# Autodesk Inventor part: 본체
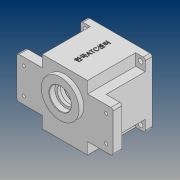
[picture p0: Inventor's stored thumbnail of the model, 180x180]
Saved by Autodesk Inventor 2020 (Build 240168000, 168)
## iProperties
Created: 2020-07
Part Number: 본체
Material: 일반
Document SubType Name: Modeling
Designer: PC312-
Density: 1 g/cm^3
Appearance: 기본값
Mass: 324.617 g
Surface Area: 793.597 cm^2
Volume: 324.617 cm^3
Author: PC312-
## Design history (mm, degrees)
sketch "스케치2"
  geometry: L1 (-47, 47)-(47, 47); L2 (47, 47)-(47, -47); L3 (47, -47)-(-47, -47); L4 (-47, -47)-(-47, 47); L5 (-47, 47)-(47, -47); L6 (47, 47)-(-47, -47); 1 further point
  constraints: 12 end point, 2 midpoint, 2 parallel, 1 horizontal, 1 perpendicular
  dimensions: "d0" = 94 distance of L2.end L3.end; "d1" = 94 distance of L1.end L2.end
extrude "돌출1" new body sketch "스케치2" stored distance "d2" = 80; taper "d3" = 0 deg
sketch "스케치3"
  geometry: L1 (-70, 30)-(70, 30); L2 (70, 30)-(70, -30); L3 (70, -30)-(-70, -30); L4 (-70, -30)-(-70, 30); L5 (-70, 30)-(70, -30); L6 (70, 30)-(-70, -30); 1 further point
  constraints: 12 end point, 2 midpoint, 2 parallel, 1 horizontal, 1 perpendicular
  dimensions: "d4" = 140 distance of L2.end L3.end; "d5" = 60 distance of L1.end L2.end
extrude "돌출2" join sketch "스케치3" distance "d6" = 13; taper "d7" = 0 deg
sketch "스케치4"
  geometry: L1 (47, 47)-(-47, 47) reference; L2 (33, 47)-(33, 30); L3 (33, 30)-(49.544, 30); L4 (70, 30)-(47, 30) reference; L5 (47, 30)-(47, 47) reference; L6 (-47, -47)-(-47, 47) reference; L7 (-47, 30)-(-33, 30); L8 (-33, 47)-(-33, 30); 2 further points
  constraints: 8 end point, 4 point on line, 2 vertical, 1 horizontal
  dimensions: "d8" = 33 distance from line of L2 point (0, 0); "d9" = 30 distance from line of point (0, 0) L3; "d12" = 33 distance from line of L8 point (0, 0); "d13" = 30 distance from line of point (0, 0) L7
extrude "돌출3" cut sketch "스케치4" distance "d10" = 70; taper "d11" = 0 deg
sketch "스케치5"
  geometry: C1 r 43 at (0, 0); C2 r 40 at (0, 0); 1 further point
  constraints: 2 centre point, 2 coincident
  dimensions: "d20" = 86 diameter of C1; "d21" = 80 diameter of C2
extrude "돌출4" cut sketch "스케치5" distance "d22" = 9; taper "d23" = 0 deg
extrude "돌출5" cut sketch "스케치5" distance "d24" = 71; taper "d25" = 0 deg
sketch "스케치6"
  geometry: A1 r 21 centre (0, 11) between (8.978, -7.984) and (-8.978, -7.984); A2 r 15 centre (0, -20) between (-8.978, -7.984) and (8.978, -7.984); 1 further point
  constraints: 4 point on circle, 2 centre point, 2 vertical alignment
  dimensions: "d26" = 42 diameter of A1; "d27" = 30 diameter of A2; "d28" = 11 distance of point (0, 0) A1.centre; "d29" = 20 distance of A2.centre point (0, 0)
extrude "돌출6" join sketch "스케치6" distance "d30" = 7; taper "d31" = 0 deg
sketch "스케치7"
  geometry: C1 r 17.5 at (0, 11); C2 r 11 at (0, -20); C3 r 12.5 at (0, 11); C4 r 9.5 at (0, -20); A1 r 21 centre (0, 11) between (8.978, -7.984) and (-8.978, -7.984) reference; A2 r 15 centre (0, -20) between (-8.978, -7.984) and (8.978, -7.984) reference; 1 further point
  constraints: 4 centre point, 4 coincident
  dimensions: "d32" = 35 diameter of C1; "d33" = 22 diameter of C2; "d34" = 25 diameter of C3; "d35" = 19 diameter of C4
extrude "돌출7" cut sketch "스케치7" distance "d36" = 10; taper "d37" = 0 deg
extrude "돌출8" cut sketch "스케치7" distance "d38" = 14.7; taper "d39" = 0 deg
extrude "돌출11" cut sketch "스케치7" distance "d44" = 7; taper "d45" = 0 deg
extrude "돌출12" cut sketch "스케치7" distance "d46" = 10; taper "d47" = 0 deg
sketch "스케치8"
  geometry: C1 r 27.5 at (0, 11); 1 further point
  constraints: 1 centre point, 1 vertical alignment
  dimensions: "d48" = 55 diameter of C1; "d49" = 11 distance of point (0, 0) C1.centre
extrude "돌출13" join sketch "스케치8" distance "d50" = 7; taper "d51" = 0 deg
sketch "스케치9"
  geometry: C1 r 27.5 at (0, 0) reference; C2 r 16 at (0, 0); 1 further point
  constraints: 1 centre point, 1 coincident
  dimensions: "d52" = 32 diameter of C2
extrude "돌출14" cut sketch "스케치9" distance "d53" = 8.3; taper "d54" = 0 deg
sketch "스케치10"
  geometry: A1 r 4 centre (-36, 0) between (-36.19, -3.995) and (-36.19, 3.995); A2 r 3 centre (-36.333, 6.992) between (-39.279, 7.559) and (-36.19, 3.995); A3 r 3 centre (-36.333, -6.992) between (-36.19, -3.995) and (-39.279, -7.559); A4 r 40 centre (0, 0) between (-39.279, 7.559) and (-39.279, -7.559) reference; 1 further point
  constraints: 8 point on circle, 4 tangent, 3 centre point, 1 horizontal alignment
  dimensions: "d55" = 8 diameter of A1; "d56" = 36 distance of point (0, 0) A1.centre; "d57" = 6 diameter of A2; "d58" = 6 diameter of A3
extrude "돌출15" join sketch "스케치10" distance "d59" = 62; taper "d60" = 0 deg
sketch "스케치11"
  geometry: C1 r 3.5 at (-40, 40); 1 further point
  constraints: 1 centre point
  dimensions: "d61" = 7 diameter of C1; "d62" = 40 horizontal distance of C1.centre point (0, 0); "d63" = 40 horizontal distance of C1.centre point (0, 0)
extrude "돌출16" cut sketch "스케치11" extent not by distance; stored distance "d64" = 0; taper "d65" = 0 deg
sketch "스케치12"
  geometry: 2 further points
  dimensions: "d72" = 60 horizontal distance of point (-60, 19) point (0, 0); "d73" = 19 vertical distance of point (-60, 19) point (0, 0)
hole "구멍1" sketch "스케치12" at (-60, 19) diameter "d74" = 4.5; stored, may be unused: countersink angle "d78" = 90 deg, drill point angle "d80" = 118 deg; dims "d75" = 7, "d76" = 10, "d77" = 5, "d79" = 9
sketch "스케치13"
  geometry: A1 r 4 centre (-36, 0) between (-36.19, -3.995) and (-36.19, 3.995) reference; 2 further points
  constraints: 1 coincident
hole "구멍2" sketch "스케치13" at (-36, 0) diameter "d87" = 3.242; stored, may be unused: countersink angle "d91" = 90 deg, drill point angle "d93" = 118 deg; dims "d88" = 7, "d89" = 10, "d90" = 5, "d92" = 9
node "작업 평면1"
sketch "스케치15"
  geometry: L1 (0, 0)-(94, 0) reference; 2 further points
  constraints: 1 coincident, 1 other
  dimensions: "d95" = 40 distance from line of L1 point (47, -40)
feature "엠보싱1" sketch "스케치15" dims "d8" = 33, "d9" = 30, "d96" = 0.5, "d97" = 0
chamfer "모따기2" distance "d101" = 1; stored, may be unused: second distance "d102" = 2, angle "d103" = 30 deg
chamfer "모따기3" distance "d104" = 1; stored, may be unused: second distance "d105" = 2, angle "d106" = 30 deg
fillet "모깎기1" dims "d107" = 3
fillet "모깎기2" dims "d108" = 3
fillet "모깎기3" dims "d109" = 3
chamfer "모따기4" distance "d110" = 0.8; stored, may be unused: second distance "d111" = 2, angle "d112" = 30 deg
node "솔리드1"
pattern_linear "직사각형 패턴1" dims "d16" = 80, "d19" = 77
mirror "미러1"
pattern_linear "직사각형 패턴2" dims "d68" = 80, "d71" = 80
pattern_linear "직사각형 패턴3" dims "d83" = 120, "d86" = 38
mirror "미러2"
feature "A9D066F2-1C7D-4E18-AEED-F7BC21143FA4" dims "d74" = 4.5, "d75" = 7, "d76" = 10, "d77" = 5, "d78" = 90 deg, "d79" = 9, "d80" = 118 deg
other parameters: "d94" = 0.5
